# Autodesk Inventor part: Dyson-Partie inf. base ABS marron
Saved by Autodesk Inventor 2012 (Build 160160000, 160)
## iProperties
Created: 2012-11
Part Number: Dyson-Partie inf. base ABS marron
Material: Default
Document SubType Name: Modeling
Designer: Administrateur
Density: 1 g/cm^3
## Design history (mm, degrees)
node "Dyson-Partie inf. base ABS marron1"
node "Dyson-Partie inf. base ABS marron"
node "Dyson-Partie inf. base ABS marron_1"
node "Base1"
node "Base2"
